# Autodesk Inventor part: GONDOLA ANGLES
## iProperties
Shininess: 64.0
Length Units: 11272
Angle Units: 11279
Time Units: 11290
Mass Units: 11286
Length Display Precision: 3
Angle Display Precision: 2
Compacted: True
Part Number: GONDOLA ANGLES
Document SubType Name: Modeling
Created: 2004-08
Designer: John Blackburn
Manufacturer: Standard
Standards Organization: Custom
Density: 0.0
Volumn: 0.0
Area: 0.0
PropertySet Name: Model Information
Control State: 0
Master: False
Checked Out: False
Author: John Blackburn
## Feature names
1. ExtrusionBlind1
